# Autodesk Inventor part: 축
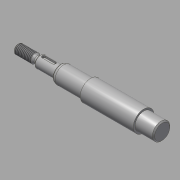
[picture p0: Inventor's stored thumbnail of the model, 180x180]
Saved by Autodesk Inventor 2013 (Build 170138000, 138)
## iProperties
Created: 2015-11
Part Number: 축
Material: 강철, 연강
Document SubType Name: Modeling
Designer: mduedu
Density: 1 g/cm^3
Author: mduedu
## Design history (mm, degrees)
sketch "스케치1"
  geometry: L1 (-86, 0)-(86, 0); L2 (-86, 0)-(-86, 4); L3 (-86, 4)-(-70.732, 4); L4 (-70.732, 4)-(-69, 3); L5 (-69, 3)-(-67, 3); L6 (-67, 3)-(-67, 5); L7 (-67, 5)-(-49, 5); L8 (-49, 5)-(-49, 6.55); L9 (-47.355, 7.5)-(-23, 7.5); L10 (-23, 7.5)-(-23, 9); L11 (0, 0)-(0, 9); L12 (86, 4)-(70.732, 4); L13 (70.732, 4)-(69, 3); L14 (69, 3)-(67, 3); L15 (67, 3)-(67, 5); L16 (67, 5)-(49, 5); L17 (23, 7.5)-(23, 9); L18 (86, 0)-(86, 4); L19 (-23, 9)-(23, 9); L20 (-49, 6.55)-(-47.355, 7.5); L21 (47.355, 7.5)-(23, 7.5); L22 (49, 6.55)-(47.355, 7.5); L23 (49, 5)-(49, 6.55); 1 further point
  constraints: 46 end point, 10 symmetric about line, 6 perpendicular, 5 parallel, 2 midpoint, 1 coincident, 1 horizontal
  dimensions: "d0" = 172 distance of L1.start L1.end (derived); "d1" = 8 diameter of L3 L1; "d2" = 30 deg angle of L4 L5; "d3" = 6 diameter of L5 L1; "d4" = 10 diameter of L7 L1; "d5" = 15 diameter of L9 L1; "d6" = 18 diameter of L19 L1; "d8" = 18 distance of L6.end L7.end; "d9" = 46 distance of L10.end L17.end; "d10" = 2 distance of L4.end L5.end; "d11" = 17 distance from line of L4.end L2; "d16" = 13.1 diameter of L8.end L1; "d17" = 30 deg angle of L20 L9; "d18" = 26 distance between parallel lines of L10 L8
revolve "회전1" sketch "스케치1" stored, may be unused: angle "d12" = 90 deg
chamfer "모따기1" distance "d13" = 1; stored, may be unused: second distance "d14" = 2, angle "d15" = 45 deg
fillet "모깎기1" dims "d19" = 4, "d20" = 0.5
node "작업 평면1"
sketch "스케치2" dims "d23" = 12
  geometry: L1 (-5.5, 1.5)-(3.5, 1.5); L2 (3.5, 1.5)-(3.5, -1.5); L3 (3.5, -1.5)-(-5.5, -1.5); L4 (-5.5, -1.5)-(-5.5, 1.5); L5 (-9, -4)-(-9, 4) reference; 3 further points
  constraints: 8 end point, 2 midpoint, 2 parallel, 2 vertical alignment, 1 horizontal, 1 perpendicular, 4 other
  dimensions: "d21" = 3 distance between parallel lines of L3 L1; "d24" = 2 dimension on L5
extrude "돌출1" cut sketch "스케치2" distance "d25" = 1.8; taper "d26" = 0 deg
feature "스레드1" dims "d27" = 10, "d28" = 0
feature "스레드2" dims "d29" = 10, "d30" = 0
chamfer "모따기2" distance "d31" = 1; stored, may be unused: second distance "d32" = 2, angle "d33" = 45 deg
node "작업 평면2"
sketch "스케치3"
  geometry: C1 r 7.5 at (0, 0) reference; 1 further point
extrude "돌출2" cut sketch "스케치3" stored distance "d36" = 10; taper "d37" = 0 deg
chamfer "모따기3" distance "d38" = 1; stored, may be unused: second distance "d39" = 2, angle "d40" = 45 deg
node "솔리드1"
mirror "대칭1"
node "절단 모서리 투영1"
other parameters: "d35" = 16
